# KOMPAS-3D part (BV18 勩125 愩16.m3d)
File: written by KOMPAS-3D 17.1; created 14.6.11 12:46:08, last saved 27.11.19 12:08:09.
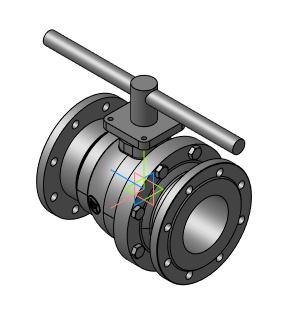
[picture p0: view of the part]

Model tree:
1. Плоскость XY
2. Плоскость ZX
3. Плоскость ZY
4. Ось X
5. Ось Y
6. Ось Z
7. Начало координат
8. Операция без истории:2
